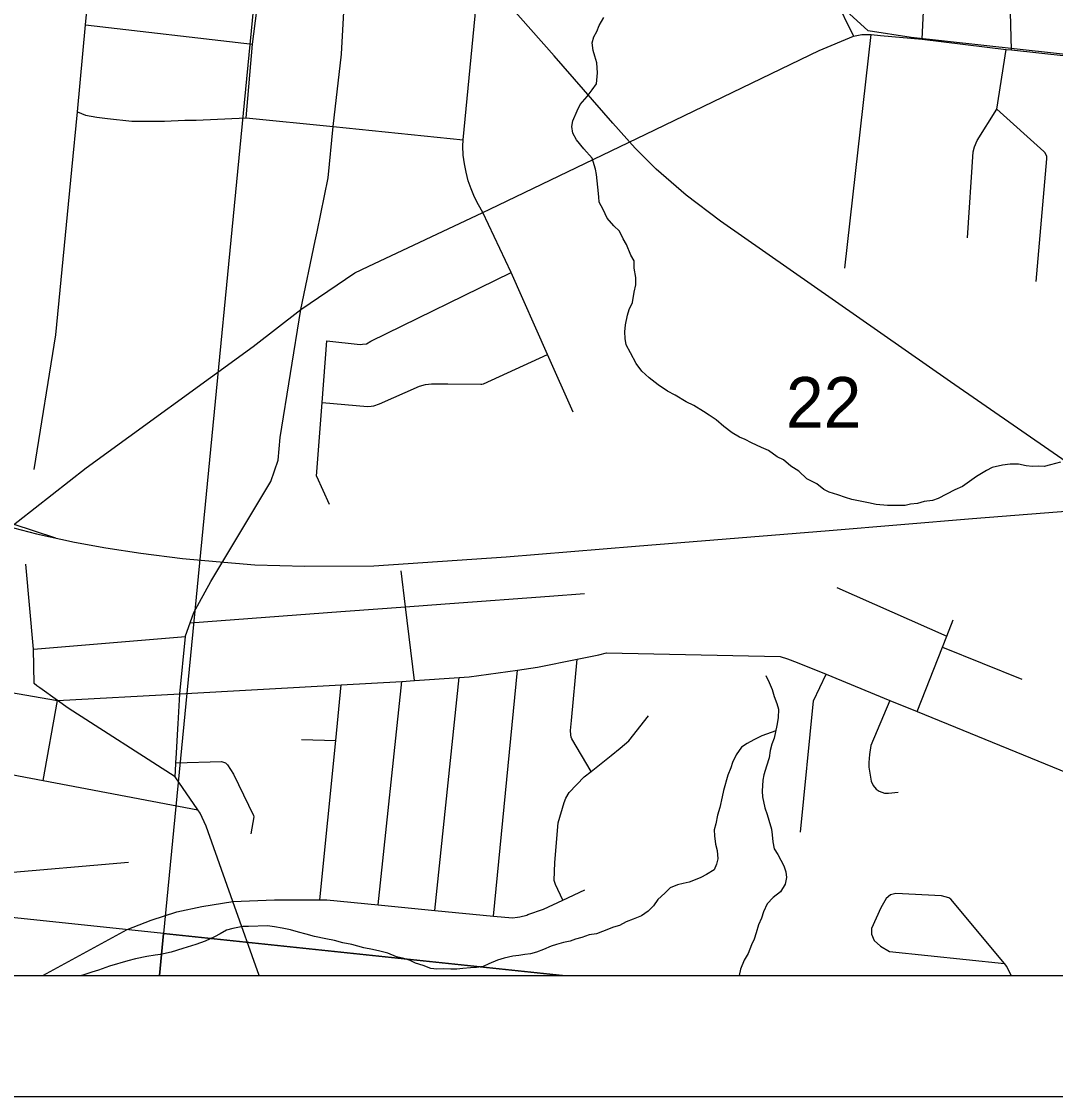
# Model space of a CAD drawing. Extents: x 0 to 34, y -3.9 to 26.2.
# Drawn here: x 4.481 to 5.335, y 14 to 14.888 of the extents above; entities that cross this region are included whole.
import ezdxf

# ---------------------------------------------------------------- set-up
doc = ezdxf.new("R2010")
doc.units = 0
for name, color, linetype in [('GM_X_City_Street', 7, 'Continuous'), ('GM_X_County_Road', 7, 'Continuous'), ('GM_X_Interchange_Ramps', 7, 'Continuous'), ('GM_X_Interstate_Route', 7, 'Continuous'), ('GM_X_Minor_River', 7, 'Continuous'), ('GM_X_Rail_Line', 7, 'Continuous'), ('GM_X_Section', 7, 'Continuous'), ('GM_X_Section_Text', 7, 'Continuous'), ('GM_X_State_Shield', 7, 'Continuous'), ('SH_Data', 7, 'Continuous')]:
    doc.layers.add(name, color=color, linetype=linetype)

msp = doc.modelspace()

# ---------------------------------------------------------------- linework, layer by layer
at = {"layer": 'GM_X_City_Street'}
for p, q in [((5.22488, 14.87348), (5.22871, 14.95344)), ((4.53354, 14.88538), (4.67148, 14.86939)), ((5.16089, 14.68433), (5.18263, 14.87726)), ((4.72432, 14.51234), (4.73473, 14.48921)), ((5.15432, 14.42053), (5.24507, 14.38029)), ((4.49061, 14.36945), (4.61612, 14.37994)), ((5.24152, 14.37122), (5.30701, 14.34464)), ((4.87074, 14.14907), (4.89045, 14.3523)), ((4.7754, 14.15827), (4.79497, 14.34287)), ((4.82224, 14.15375), (4.84218, 14.34608)), ((4.49867, 14.261), (4.51053, 14.32704)), ((4.71208, 14.29504), (4.74026, 14.294)), ((4.43505, 14.18205), (4.56917, 14.1937))]:
    msp.add_line(p, q, dxfattribs=at)
for points in [[(5.29869, 14.8646), (5.2974, 14.90603), (5.31251, 14.91817), (5.32221, 14.92665), (5.32554, 14.93059), (5.32715, 14.93286), (5.32772, 14.93449), (5.33327, 14.97423), (5.33475, 14.99748), (5.33465, 14.99927), (5.32991, 15.00738), (5.3109, 15.03675), (5.31401, 15.07261)], [(4.66633, 14.80845), (4.67148, 14.86939), (4.67975, 14.93379), (4.68411, 14.99182), (4.68809, 15.05618), (4.68905, 15.06222)], [(4.86175, 14.73033), (4.85812, 14.73657), (4.85492, 14.74304), (4.85215, 14.7497), (4.84983, 14.75654), (4.84797, 14.76351), (4.84658, 14.77059), (4.84566, 14.77775), (4.84522, 14.78495), (4.84562, 14.79021), (4.85711, 14.91012)], [(5.31896, 14.67332), (5.3279, 14.77472), (5.32769, 14.77655), (5.32713, 14.77788), (5.32615, 14.77977), (5.32542, 14.78068), (5.28642, 14.81552), (5.29426, 14.86493)], [(4.52701, 14.8133), (4.53358, 14.81076), (4.54294, 14.80897), (4.55171, 14.80798), (4.57177, 14.8057), (4.59881, 14.80585), (4.61558, 14.80646), (4.61747, 14.80656), (4.61939, 14.80663), (4.62131, 14.80665), (4.6232, 14.80664), (4.62512, 14.8066), (4.66633, 14.80845), (4.73828, 14.80133)], [(5.26214, 14.7094), (5.26694, 14.78032), (5.26801, 14.78448), (5.27021, 14.78973), (5.28642, 14.81552)], [(4.93635, 14.56543), (4.91523, 14.61306), (4.88522, 14.68073), (4.86175, 14.73033)], [(4.73292, 14.62416), (4.76055, 14.62113), (4.76231, 14.62139), (4.76583, 14.6219), (4.76935, 14.62393), (4.88522, 14.68073)], [(4.72432, 14.51234), (4.72902, 14.57339), (4.73292, 14.62416)], [(4.72902, 14.57339), (4.76643, 14.57007), (4.7696, 14.57021), (4.77186, 14.57069), (4.77636, 14.57208), (4.80938, 14.58675), (4.81452, 14.58821), (4.81929, 14.58875), (4.83296, 14.58876), (4.86017, 14.58835), (4.86104, 14.58837), (4.86229, 14.58885), (4.91523, 14.61306)], [(4.80533, 14.34357), (4.79789, 14.40452), (4.79426, 14.43425)], [(4.83447, 14.40724), (4.917, 14.41337), (4.94574, 14.4155)], [(4.74848, 14.40086), (4.79789, 14.40452), (4.83076, 14.40696), (4.83447, 14.40724)], [(4.61997, 14.39132), (4.74453, 14.40056), (4.74848, 14.40086)], [(5.22069, 14.31804), (5.24152, 14.37122), (5.24507, 14.38029), (5.25034, 14.39373)], [(4.9512, 14.26858), (4.93531, 14.29554), (4.93488, 14.29685), (4.93452, 14.2987), (4.93435, 14.30241), (4.93494, 14.31075), (4.93981, 14.36136)], [(5.12425, 14.21834), (5.13492, 14.32673), (5.14533, 14.34885)], [(4.7272, 14.16238), (4.74026, 14.294), (4.74484, 14.34007)], [(5.19811, 14.32727), (5.18242, 14.28991), (5.18126, 14.2824), (5.18076, 14.27592), (5.18076, 14.27209), (5.18259, 14.26062), (5.18432, 14.25681), (5.18675, 14.25397), (5.18915, 14.25213), (5.19366, 14.2505), (5.19689, 14.25047), (5.20506, 14.25137)], [(4.92793, 14.16224), (4.92176, 14.17504), (4.92088, 14.17854), (4.92126, 14.19334), (4.92401, 14.22594), (4.929, 14.2429), (4.93038, 14.24645), (4.93302, 14.25116), (4.9455, 14.26411), (4.9512, 14.26858), (4.96798, 14.28173), (4.97535, 14.28762), (4.98235, 14.29388), (4.99882, 14.31433)], [(4.38337, 14.28273), (4.49867, 14.261), (4.5291, 14.25526), (4.62625, 14.23695)], [(4.60816, 14.27558), (4.64589, 14.27683), (4.64924, 14.27563), (4.65075, 14.27403), (4.65587, 14.26629), (4.67244, 14.23203), (4.67251, 14.23107), (4.67015, 14.21689)], [(4.89037, 14.14816), (4.89242, 14.14845), (4.89811, 14.1499), (4.89909, 14.15026), (4.9119, 14.15485), (4.92793, 14.16224), (4.9461, 14.17063)], [(5.2984, 14.1), (5.29465, 14.10746), (5.2927, 14.1098), (5.24849, 14.16295), (5.24669, 14.1642), (5.24066, 14.16587), (5.20311, 14.16763), (5.19859, 14.16662), (5.19504, 14.16366), (5.19067, 14.15579), (5.18303, 14.1389), (5.18293, 14.13408), (5.18506, 14.12897), (5.19026, 14.12427), (5.19775, 14.11989), (5.2927, 14.1098)], [(4.6553, 14.16113), (4.68961, 14.16241), (4.7272, 14.16238), (4.73289, 14.16238), (4.7754, 14.15827), (4.82224, 14.15375), (4.87074, 14.14907), (4.88628, 14.14757), (4.89037, 14.14816)]]:
    msp.add_lwpolyline(points, dxfattribs=at)
at = {"layer": 'GM_X_County_Road'}
for p, q in [((5.14505, 14.92322), (5.16799, 14.87594)), ((4.73828, 14.80133), (4.84562, 14.79021))]:
    msp.add_line(p, q, dxfattribs=at)
for points in [[(4.52233, 14.76557), (4.52701, 14.8133), (4.53354, 14.88538), (4.53966, 14.9475), (4.54189, 15.03617), (4.54239, 15.0525), (4.54313, 15.06264)], [(4.72499, 14.71442), (4.73411, 14.75883), (4.73828, 14.80133), (4.74493, 14.86118), (4.74846, 14.92122), (4.7477, 14.92987), (4.74623, 14.93538), (4.74128, 14.94773)], [(4.99646, 14.79494), (5.13955, 14.8641), (5.16799, 14.87594), (5.1749, 14.87726), (5.18263, 14.87726), (5.19035, 14.8766), (5.22488, 14.87348), (5.29426, 14.86493), (5.29869, 14.8646), (5.43907, 14.84929), (5.59265, 14.83254), (5.59845, 14.83196)], [(4.76717, 14.68573), (4.86175, 14.73033), (4.86747, 14.73297), (4.98206, 14.78798), (4.99646, 14.79494)], [(4.49119, 14.5181), (4.50896, 14.62908), (4.52233, 14.76557)], [(4.61001, 14.30786), (4.61143, 14.33265), (4.61612, 14.37994), (4.6162, 14.38067), (4.61997, 14.39132), (4.62302, 14.39992), (4.63718, 14.42546), (4.6866, 14.50806), (4.69264, 14.52579), (4.69452, 14.54437), (4.71144, 14.65021), (4.72343, 14.70684), (4.72499, 14.71442)], [(4.5342, 14.51924), (4.67199, 14.61964), (4.71144, 14.65021), (4.756, 14.68046), (4.76717, 14.68573)], [(4.32838, 14.36169), (4.37935, 14.39819), (4.5342, 14.51924)], [(4.49345, 14.3393), (4.49114, 14.34106), (4.49061, 14.36945), (4.48421, 14.43965)], [(4.32838, 14.36169), (4.34529, 14.35566), (4.51053, 14.32704), (4.61143, 14.33265), (4.74484, 14.34007), (4.79497, 14.34287), (4.80533, 14.34357), (4.84218, 14.34608), (4.85054, 14.34665), (4.89045, 14.3523), (4.90688, 14.35462), (4.93981, 14.36136), (4.95757, 14.36499), (4.96405, 14.36638), (5.1075, 14.36346), (5.11354, 14.36144), (5.12146, 14.35862), (5.14533, 14.34885), (5.19811, 14.32727), (5.22069, 14.31804), (5.36404, 14.25943)], [(4.60751, 14.2642), (4.51925, 14.32081), (4.51053, 14.32704), (4.49576, 14.33754), (4.49345, 14.3393)], [(4.60862, 14.28362), (4.60977, 14.30373), (4.61001, 14.30786)], [(4.67691, 14.1), (4.6553, 14.16113), (4.63329, 14.22339), (4.62819, 14.23414), (4.62625, 14.23695), (4.60751, 14.2642), (4.60811, 14.2748), (4.60816, 14.27558), (4.60862, 14.28362)], [(4.49826, 14.1), (4.56788, 14.13809), (4.58776, 14.14567), (4.60915, 14.15245), (4.62974, 14.15697), (4.6553, 14.16113)]]:
    msp.add_lwpolyline(points, dxfattribs=at)
at = {"layer": 'GM_X_Interchange_Ramps'}
msp.add_lwpolyline([(3.56816, 14.1), (7.29135, 14.1)], dxfattribs=at)
at = {"layer": 'GM_X_Interstate_Route'}
msp.add_lwpolyline([(2.54681, 14.1), (8.9, 14.1)], dxfattribs=at)
at = {"layer": 'GM_X_Minor_River'}
for points in [[(4.93964, 14.81435), (4.94212, 14.81957), (4.94808, 14.82616), (4.9521, 14.8317), (4.95571, 14.83649), (4.95645, 14.84559), (4.95602, 14.85396), (4.95433, 14.85936), (4.953, 14.86397), (4.95211, 14.87047), (4.95344, 14.87536), (4.9559, 14.87982), (4.95799, 14.88467), (4.96167, 14.89136)], [(5.339, 14.52405), (5.33093, 14.52173), (5.32556, 14.52043), (5.32101, 14.52062), (5.31606, 14.52044), (5.31076, 14.52104), (5.30436, 14.52245), (5.29752, 14.52235), (5.29102, 14.52148), (5.28258, 14.51955), (5.27793, 14.51709), (5.26975, 14.5121), (5.26389, 14.50817), (5.25802, 14.50385), (5.25183, 14.50106), (5.23788, 14.49404), (5.23325, 14.49233), (5.22637, 14.49147), (5.22099, 14.4898), (5.21527, 14.48928), (5.21067, 14.48833), (5.20458, 14.4882), (5.19622, 14.48817), (5.18675, 14.48894), (5.18035, 14.49035), (5.16678, 14.49319), (5.16153, 14.49493), (5.15515, 14.4971), (5.14802, 14.49929), (5.14354, 14.50138), (5.13765, 14.50618), (5.12945, 14.51033), (5.12286, 14.51668), (5.11618, 14.52076), (5.11031, 14.52595), (5.10508, 14.52845), (5.09769, 14.5337), (5.09209, 14.53621), (5.08388, 14.53997), (5.07867, 14.54285), (5.0738, 14.54457), (5.06786, 14.54824), (5.06085, 14.55347), (5.05461, 14.55906), (5.04867, 14.56272), (5.04424, 14.56595), (5.03607, 14.57085), (5.02973, 14.57377), (5.02083, 14.57947), (5.0145, 14.58277), (5.00673, 14.58803), (4.99935, 14.59367), (4.99311, 14.59925), (4.98841, 14.60552), (4.98383, 14.61446), (4.98029, 14.62107), (4.97934, 14.62605), (4.97919, 14.63176), (4.97979, 14.63743), (4.98124, 14.64536), (4.98258, 14.65024), (4.98546, 14.65583), (4.98694, 14.66451), (4.98832, 14.67053), (4.98818, 14.67662), (4.98696, 14.68427), (4.98682, 14.69036), (4.98396, 14.69504), (4.98051, 14.70393), (4.97765, 14.70861), (4.97486, 14.71481), (4.97009, 14.71919), (4.96464, 14.7255), (4.96113, 14.73287), (4.95794, 14.7387), (4.95774, 14.74327), (4.95692, 14.75129), (4.9558, 14.7616), (4.95484, 14.7662), (4.95215, 14.77506), (4.94524, 14.78295), (4.93908, 14.79042), (4.93625, 14.79586), (4.93532, 14.80122), (4.93628, 14.80613), (4.93964, 14.81435)], [(5.09569, 14.34788), (5.0985, 14.34206), (5.10093, 14.33626), (5.1026, 14.33049), (5.10465, 14.3247), (5.10599, 14.32008), (5.10571, 14.31287), (5.10469, 14.30645), (5.10372, 14.30117), (5.10238, 14.2959), (5.10067, 14.29103), (5.09932, 14.28576), (5.09832, 14.27972), (5.09615, 14.27297), (5.09397, 14.26584), (5.09303, 14.26131), (5.09268, 14.2522), (5.09288, 14.24763), (5.09479, 14.23843), (5.09686, 14.23302), (5.0982, 14.2284), (5.10018, 14.22072), (5.10076, 14.21613), (5.10129, 14.21041), (5.10258, 14.20465), (5.10544, 14.19997), (5.11039, 14.19064), (5.11209, 14.18563), (5.11267, 14.18104), (5.11169, 14.17538), (5.10764, 14.16908), (5.10176, 14.16439), (5.09661, 14.15928), (5.09369, 14.15256), (5.09196, 14.14731), (5.08946, 14.14171), (5.08769, 14.13532), (5.08596, 14.13007), (5.08387, 14.12521), (5.08093, 14.11811), (5.07767, 14.11254), (5.07472, 14.10506), (5.07356, 14.1)], [(5.10389, 14.30206), (5.09219, 14.29784), (5.08561, 14.2947), (5.08016, 14.2915), (5.07549, 14.28865), (5.07106, 14.28237), (5.06815, 14.27603), (5.06684, 14.27152), (5.06432, 14.26554), (5.06078, 14.25277), (5.05943, 14.2475), (5.05757, 14.23883), (5.05579, 14.23245), (5.05437, 14.22528), (5.05304, 14.22039), (5.05322, 14.21544), (5.05409, 14.20857), (5.0554, 14.20319), (5.05589, 14.19632), (5.05495, 14.1918), (5.05288, 14.18733), (5.04664, 14.1834), (5.04198, 14.18094), (5.03734, 14.17885), (5.03233, 14.17716), (5.02734, 14.17584), (5.02274, 14.17489), (5.01657, 14.17249), (5.01222, 14.16811), (5.0063, 14.16265), (5.00268, 14.15748), (4.99833, 14.1531), (4.99285, 14.14914), (4.9859, 14.14639), (4.98012, 14.14435), (4.97467, 14.14115), (4.96968, 14.13984), (4.9608, 14.13641), (4.95578, 14.13434), (4.94967, 14.13345), (4.94351, 14.13142), (4.93851, 14.13011), (4.93389, 14.1284), (4.92851, 14.1271), (4.92275, 14.12544), (4.91814, 14.12411), (4.91195, 14.12133), (4.90617, 14.11929), (4.90117, 14.11797), (4.89659, 14.1174), (4.89161, 14.11647), (4.88665, 14.11592), (4.87937, 14.11432), (4.87398, 14.11264), (4.86664, 14.10953), (4.862, 14.10744), (4.85664, 14.10652), (4.85169, 14.10634), (4.84521, 14.10585), (4.84025, 14.1053), (4.8353, 14.10512), (4.82923, 14.10538), (4.82391, 14.10522), (4.81899, 14.1058), (4.81263, 14.10835), (4.80624, 14.11013), (4.80176, 14.11222), (4.79651, 14.11396), (4.79049, 14.11535), (4.78338, 14.11831), (4.77661, 14.12011), (4.77059, 14.1215), (4.76342, 14.12293), (4.75365, 14.12562), (4.74611, 14.12708), (4.73933, 14.12888), (4.73217, 14.13032), (4.72275, 14.13223), (4.71598, 14.13403), (4.70959, 14.13582), (4.70282, 14.13762), (4.69603, 14.13904), (4.68961, 14.14007), (4.68395, 14.14106), (4.66835, 14.14057), (4.66341, 14.14039), (4.65536, 14.13883), (4.64999, 14.13753), (4.64493, 14.13432), (4.64027, 14.13185), (4.63253, 14.12837), (4.62482, 14.12565), (4.61405, 14.1223), (4.60443, 14.11927), (4.59561, 14.11736), (4.59103, 14.11679), (4.58414, 14.11555), (4.57495, 14.11366), (4.56842, 14.11203), (4.55343, 14.10771), (4.54418, 14.10429)], [(4.54418, 14.10429), (4.53879, 14.10261), (4.53148, 14.10025), (4.53024, 14.1)]]:
    msp.add_lwpolyline(points, dxfattribs=at)
at = {"layer": 'GM_X_Rail_Line'}
for points in [[(6.22888, 14.76326), (5.21557, 14.8749), (5.18022, 14.88026), (5.14629, 14.91135), (5.05275, 15.09861), (5.02186, 15.13272), (4.97316, 15.15786), (4.93075, 15.16415), (4.87734, 15.172), (4.74853, 15.183), (4.69669, 15.16257), (4.66999, 15.13113), (4.66816, 15.12896)], [(5.36247, 14.51126), (5.24823, 14.59044), (5.05827, 14.72306), (5.0297, 14.74453), (5.0051, 14.76601), (4.98758, 14.78353), (4.96924, 14.80396), (4.92086, 14.85963), (4.74311, 15.06041)], [(3.45648, 14.86993), (3.65667, 14.78629), (3.72369, 14.75988), (3.83713, 14.71468), (3.97105, 14.66128), (4.18709, 14.57537), (4.31213, 14.52536), (4.35914, 14.50753), (4.40892, 14.48947), (4.46785, 14.47141), (4.49298, 14.46492), (4.52447, 14.45798), (4.5504, 14.45335), (4.57935, 14.44895), (4.61362, 14.44455), (4.6414, 14.442), (4.67359, 14.43922), (4.71481, 14.43806), (4.77167, 14.43843), (4.88097, 14.44577), (4.98806, 14.45458), (5.14781, 14.4677), (5.26637, 14.47743), (5.39569, 14.48768)], [(4.45511, 14.47894), (4.4735, 14.47315), (4.50879, 14.46143)]]:
    msp.add_lwpolyline(points, dxfattribs=at)
at = {"layer": 'GM_X_Section'}
msp.add_lwpolyline([(3.68487, 15.24697), (4.69633, 15.14722), (4.59807, 14.13459), (3.58071, 14.24166)], close=True, dxfattribs=at)
at = {"layer": 'GM_X_State_Shield'}
for points in [[(4.92768, 14.1), (5.6066, 14.1), (5.6843, 15.03017), (4.69633, 15.14722), (4.59807, 14.13459)], [(3.56807, 14.1), (4.59482, 14.1), (4.59807, 14.13459), (3.58071, 14.24166)], [(4.59482, 14.1), (4.92768, 14.1), (4.59807, 14.13459)]]:
    msp.add_lwpolyline(points, close=True, dxfattribs=at)
at = {"layer": 'SH_Data'}
msp.add_line((2, 14), (9, 14), dxfattribs=at)

# ---------------------------------------------------------------- texts
at = {"layer": 'GM_X_Section_Text'}
msp.add_text('22', height=0.041856, rotation=0.00001, dxfattribs=at).set_placement((5.11227, 14.55248))

doc.saveas('drawing.dxf')
